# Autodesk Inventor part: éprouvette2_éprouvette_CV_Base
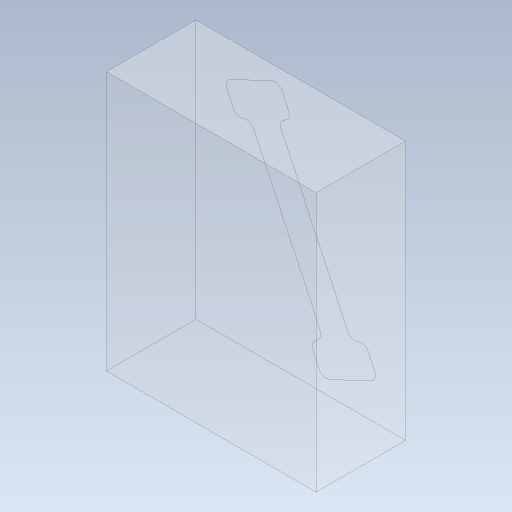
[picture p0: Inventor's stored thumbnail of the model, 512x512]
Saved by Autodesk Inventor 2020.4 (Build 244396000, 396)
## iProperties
Created: 2021-10
Part Number: éprouvette2_éprouvette_CV_Base
Material: Générique
Document SubType Name: Modeling
Designer: mel
Density: 1 g/cm^3
Appearance: Par défaut
Author: mel
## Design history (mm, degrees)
node "éprouvette2_éprouvette_MP"
feature "Solide4::éprouvette2_éprouvette_MP"
tag "FonctionRepérage1"
node "Solide1"
feature "éprouvette2_éprouvette_MP_Corps"
